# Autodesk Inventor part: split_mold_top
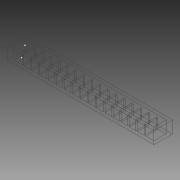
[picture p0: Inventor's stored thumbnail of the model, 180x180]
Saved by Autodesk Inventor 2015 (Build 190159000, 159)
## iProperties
Created: 2015-04
Part Number: split_mold_top
Material: Generic
Document SubType Name: Modeling
Designer: sungeun
Density: 1 g/cm^3
Appearance: Default
Author: sungeun
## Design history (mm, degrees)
sketch "Sketch1"
  geometry: L1 (-4, -7.5)-(4, -7.5); L2 (4, -7.5)-(4, 7.5); L3 (4, 7.5)-(-4, 7.5); L4 (-4, 7.5)-(-4, -7.5); L5 (-4, -7.5)-(4, 7.5); L6 (4, -7.5)-(-4, 7.5); 1 further point
  constraints: 12 end point, 2 midpoint, 2 parallel, 1 horizontal, 1 perpendicular
  dimensions: "d0" = 8 distance of L3.end L2.end; "d1" = 15 distance of L2.end L1.end
extrude "Extrusion1" new body sketch "Sketch1" distance "d2" = 15; taper "d3" = 0 deg
sketch "Sketch2"
  geometry: L1 (-3, 5.5)-(3, 5.5); L2 (3, 5.5)-(3, -5.5); L3 (3, -5.5)-(-3, -5.5); L4 (-3, -5.5)-(-3, 5.5); L5 (4, -7.5)-(4, 7.5) reference; L6 (-4, 7.5)-(-4, -7.5) reference; L7 (4, 7.5)-(-4, 7.5) reference; L8 (-4, -7.5)-(4, -7.5) reference; 1 further point
  constraints: 8 end point, 2 parallel, 1 horizontal, 1 perpendicular
  dimensions: "d4" = 1 distance between parallel lines of L5 L2; "d5" = 1 distance between parallel lines of L6 L4; "d6" = 2 distance between parallel lines of L7 L1; "d7" = 2 distance between parallel lines of L8 L3
extrude "Extrusion2" cut sketch "Sketch2" distance "d8" = 13; taper "d9" = 0 deg
sketch "Sketch3"
  geometry: L1 (0, 15)-(-15, 15) reference; L2 (-15, 0)-(-12, 0); L3 (-12, 0)-(-12, 15); L4 (-12, 15)-(-15, 15); L5 (-15, 15)-(-15, 0); L6 (-15, 0)-(-15, 15) reference; 2 further points
  constraints: 8 end point, 2 midpoint, 2 parallel, 1 coincident, 1 horizontal, 1 perpendicular, 1 point on line
  dimensions: "d17" = 3 distance of L2.start L2.end; "d18" = 15 distance of L2.end L3.end
extrude "Extrusion3" join sketch "Sketch3" distance "d11" = 2; taper "d12" = 0 deg
pattern_linear "Rectangular Pattern1"
sketch "Sketch4"
  geometry: L1 (0, 15)-(-12, 15); L2 (-12, 15)-(-12, 0); L3 (-12, 0)-(0, 0); L4 (0, 0)-(0, 15); 1 further point
  constraints: 8 end point, 2 parallel, 1 horizontal, 1 perpendicular
extrude "Extrusion4" join sketch "Sketch4" distance "d19" = 2; taper "d20" = 0 deg
sketch "Sketch5"
  geometry: 1 further point
sketch "Sketch6"
  geometry: L1 (0, 0)-(15, 0); L2 (15, 0)-(15, 15); L3 (15, 15)-(0, 15); L4 (0, 15)-(0, 0); 1 further point
  constraints: 8 end point, 2 parallel, 1 horizontal, 1 perpendicular
  dimensions: "d21" = 15 distance of L3.end L1.start; "d22" = 15 distance of L2.end L3.end
extrude "Extrusion5" join sketch "Sketch6" distance "d23" = 2; taper "d24" = 0 deg
sketch "Sketch7"
  geometry: 1 further point
sketch "Sketch8"
  geometry: L1 (3, 5.5)-(3, -5.5) reference; L2 (157, -5.5)-(157, 5.5) reference; L3 (3, 1)-(157, 1); L4 (157, 1)-(157, -1); L5 (157, -1)-(3, -1); L6 (3, -1)-(3, 1); 3 further points
  constraints: 8 end point, 2 midpoint, 2 parallel, 2 point on line, 1 coincident, 1 horizontal, 1 perpendicular
  dimensions: "d25" = 2 distance between parallel lines of L5 L3
extrude "Extrusion6" cut sketch "Sketch8" distance "d26" = 2; taper "d27" = 0 deg
sketch "Sketch9"
  geometry: L1 (-3, 5.5)-(163, 5.5); L2 (163, 5.5)-(163, -5.5); L3 (163, -5.5)-(-3, -5.5); L4 (-3, -5.5)-(-3, 5.5); L5 (164, 6.5)-(-4, 6.5); L6 (-4, 6.5)-(-4, -6.5); L7 (-4, -6.5)-(164, -6.5); L8 (164, -6.5)-(164, 6.5)
  constraints: 16 end point, 4 parallel, 2 perpendicular, 1 horizontal, 3 other
  dimensions: "d29" = 1 distance between parallel lines of L1 L5
extrude "Extrusion7" join sketch "Sketch9" distance "d30" = 2; taper "d31" = 0 deg
sketch "Sketch10"
  geometry: L1 (-3, 5.5)-(163, 5.5) reference; L2 (7, 5.5)-(3, 5.5); L3 (3, 5.5)-(3, 1); L4 (3, 1)-(7, 1); L5 (7, 1)-(7, 5.5); L6 (163, -5.5)-(-3, -5.5) reference; L7 (7, -1)-(3, -1); L8 (3, -1)-(3, -5.5); L9 (3, -5.5)-(7, -5.5); L10 (7, -5.5)-(7, -1); L11 (6, 4.5)-(4, 4.5); L12 (4, 4.5)-(4, 2); L13 (4, 2)-(6, 2); L14 (6, 2)-(6, 4.5); L15 (6, -2)-(4, -2); L16 (4, -2)-(4, -4.5); L17 (4, -4.5)-(6, -4.5); L18 (6, -4.5)-(6, -2); 3 further points
  constraints: 32 end point, 8 parallel, 4 perpendicular, 2 horizontal, 2 midpoint, 2 point on line, 1 vertical alignment, 6 other
  dimensions: "d32" = 4 distance between parallel lines of L3 L5; "d33" = 4 distance between parallel lines of L8 L10; "d34" = 4.5 distance of L7.end L8.end; "d35" = 1 distance between parallel lines of L5 L14; "d36" = 1 distance between parallel lines of L10 L18
extrude "Extrusion8" join sketch "Sketch10" distance "d37" = 2; taper "d38" = 0 deg
pattern_linear "Rectangular Pattern2" dims "d41" = 10
sketch "Sketch11"
  geometry: L1 (10, -11.5)-(-170, -11.5); L2 (-170, -11.5)-(-170, 11.5); L3 (-170, 11.5)-(10, 11.5); L4 (10, 11.5)-(10, -11.5); L5 (-156, 7.5)-(-166, 7.5) reference; L6 (-116, -7.5)-(-124, -7.5) reference; L7 (-166, -7.5)-(-166, 7.5) reference; L8 (6, 7.5)-(6, -7.5) reference; 1 further point
  constraints: 8 end point, 2 parallel, 1 horizontal, 1 perpendicular
  dimensions: "d42" = 4 distance between parallel lines of L3 L5; "d43" = 4 distance between parallel lines of L6 L1; "d44" = 4 distance between parallel lines of L2 L7; "d45" = 4 distance between parallel lines of L4 L8
extrude "Extrusion9" new body sketch "Sketch11" distance "d46" = 21; taper "d47" = 0 deg
combine "Combine1"
  body "Solid1"
sketch "Sketch13"
  geometry: L1 (-10, 11.5)-(170, 11.5); L2 (170, 11.5)-(170, -11.5); L3 (170, -11.5)-(-10, -11.5); L4 (-10, -11.5)-(-10, 11.5); 1 further point
  constraints: 8 end point, 2 parallel, 1 horizontal, 1 perpendicular
extrude "Extrusion10" cut sketch "Sketch13" distance "d48" = 6; taper "d49" = 0 deg
sketch "Sketch14"
  geometry: L1 (-3, 5.5)-(163, 5.5); L2 (163, 5.5)-(163, -5.5); L3 (163, -5.5)-(-3, -5.5); L4 (-3, -5.5)-(-3, 5.5); 1 further point
  constraints: 8 end point, 2 parallel, 1 horizontal, 1 perpendicular
extrude "Extrusion11" cut sketch "Sketch14" distance "d50" = 2; taper "d51" = 0 deg
sketch "Sketch15" dims "d57" = 10
  geometry: L1 (-3, 5.5)-(3, 5.5); L2 (3, 5.5)-(3, -5.5); L3 (3, -5.5)-(-3, -5.5); L4 (-3, -5.5)-(-3, 5.5); L5 (7, 5.5)-(13, 5.5); L6 (13, 5.5)-(13, -5.5); L7 (7, -5.5)-(7, 5.5); L8 (13, -5.5)-(7, -5.5); L9 (17, 5.5)-(23, 5.5); L10 (23, 5.5)-(23, -5.5); L11 (17, -5.5)-(17, 5.5); L12 (23, -5.5)-(17, -5.5); L13 (27, 5.5)-(33, 5.5); L14 (33, 5.5)-(33, -5.5); L15 (27, -5.5)-(27, 5.5); L16 (33, -5.5)-(27, -5.5); L17 (37, 5.5)-(43, 5.5); L18 (43, 5.5)-(43, -5.5); L19 (37, -5.5)-(37, 5.5); L20 (43, -5.5)-(37, -5.5); L21 (47, 5.5)-(53, 5.5); L22 (53, 5.5)-(53, -5.5); L23 (47, -5.5)-(47, 5.5); L24 (53, -5.5)-(47, -5.5); L25 (57, 5.5)-(63, 5.5); L26 (63, 5.5)-(63, -5.5); L27 (57, -5.5)-(57, 5.5); L28 (63, -5.5)-(57, -5.5); L29 (67, 5.5)-(73, 5.5); L30 (73, 5.5)-(73, -5.5); L31 (67, -5.5)-(67, 5.5); L32 (73, -5.5)-(67, -5.5); L33 (77, 5.5)-(83, 5.5); L34 (83, 5.5)-(83, -5.5); L35 (77, -5.5)-(77, 5.5); L36 (83, -5.5)-(77, -5.5); L37 (87, 5.5)-(93, 5.5); L38 (93, 5.5)-(93, -5.5); L39 (87, -5.5)-(87, 5.5); L40 (93, -5.5)-(87, -5.5); L41 (97, 5.5)-(103, 5.5); L42 (103, 5.5)-(103, -5.5); L43 (97, -5.5)-(97, 5.5); L44 (103, -5.5)-(97, -5.5); L45 (107, 5.5)-(113, 5.5); L46 (113, 5.5)-(113, -5.5); L47 (107, -5.5)-(107, 5.5); L48 (113, -5.5)-(107, -5.5); L49 (117, 5.5)-(123, 5.5); L50 (123, 5.5)-(123, -5.5); L51 (117, -5.5)-(117, 5.5); L52 (123, -5.5)-(117, -5.5); L53 (127, 5.5)-(133, 5.5); L54 (133, 5.5)-(133, -5.5); L55 (127, -5.5)-(127, 5.5); L56 (133, -5.5)-(127, -5.5); L57 (137, 5.5)-(143, 5.5); L58 (143, 5.5)-(143, -5.5); L59 (137, -5.5)-(137, 5.5); L60 (143, -5.5)-(137, -5.5); L61 (147, 5.5)-(153, 5.5); L62 (153, 5.5)-(153, -5.5); L63 (147, -5.5)-(147, 5.5); L64 (153, -5.5)-(147, -5.5)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; 1 further point
  constraints: 136 end point, 2 horizontal, 2 parallel, 1 collinear, 1 perpendicular, 127 other
  dimensions: "d54" = 10 distance of L1.start L5.start
extrude "Extrusion12" cut sketch "Sketch15" stored distance "d59" = 2; taper "d60" = 0 deg
body "Solid2"
